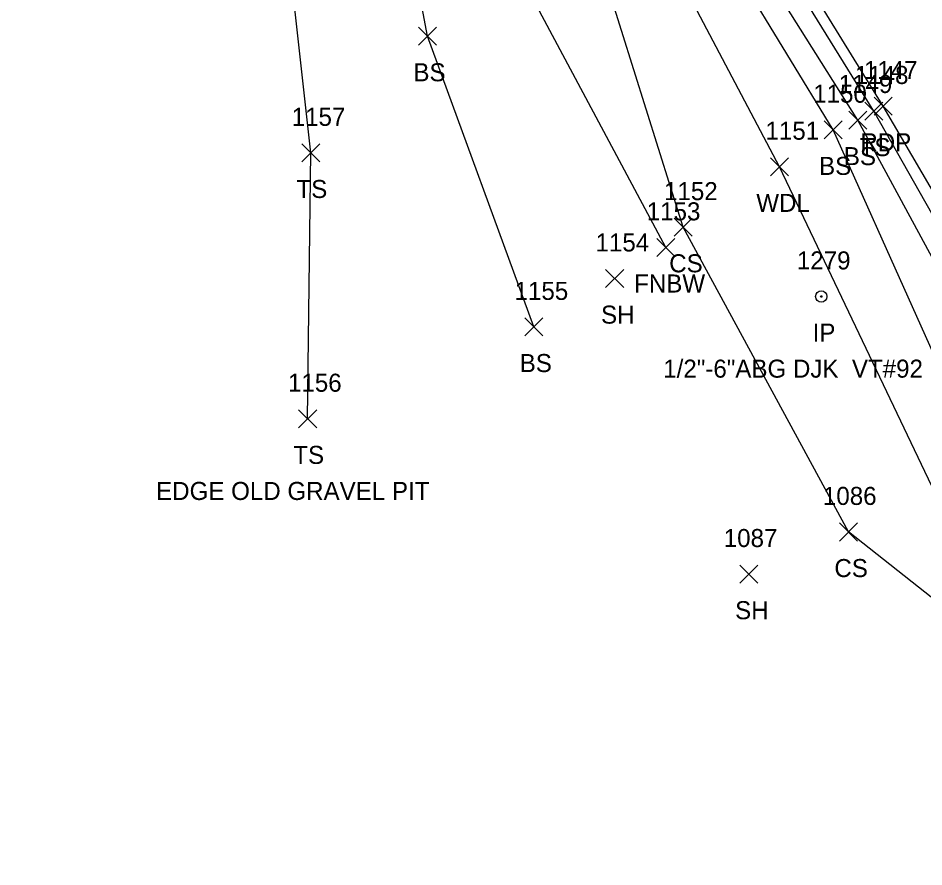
# Model space of a CAD drawing. Extents: x 1501299 to 1502485, y 381423 to 383765.
# Drawn here: x 1501751.5 to 1501851.9, y 382849.9 to 382944 of the extents above; entities that cross this region are included whole.
import ezdxf

# ---------------------------------------------------------------- set-up
doc = ezdxf.new("R2010")
doc.units = 0
for name, color, linetype in [('L_A', 7, 'Continuous'), ('L_C', 7, 'Continuous'), ('L_I', 7, 'Continuous'), ('L_TIC', 7, 'Continuous'), ('LAWA', 7, 'Continuous'), ('LELB', 7, 'Continuous'), ('LFNC', 7, 'Continuous'), ('M_A', 7, 'Continuous'), ('M_C', 7, 'Continuous'), ('M_I', 7, 'Continuous'), ('MPIR', 7, 'Continuous'), ('P_A', 7, 'Continuous'), ('P_I', 7, 'Continuous'), ('P_TIC', 7, 'Continuous'), ('PET', 7, 'Continuous')]:
    doc.layers.add(name, color=color, linetype=linetype)

msp = doc.modelspace()

# ---------------------------------------------------------------- linework, layer by layer
at = {"layer": 'L_TIC'}
for points in [[(1501795.88, 382941.03), (1501797.88, 382943.03)], [(1501797.88, 382941.03), (1501795.88, 382943.03)], [(1501845.4, 382932.73), (1501847.4, 382934.73)], [(1501847.4, 382932.73), (1501845.4, 382934.73)], [(1501843.62, 382931.73), (1501845.62, 382933.73)], [(1501845.62, 382931.73), (1501843.62, 382933.73)], [(1501840.87, 382930.65), (1501842.87, 382932.65)], [(1501842.87, 382930.65), (1501840.87, 382932.65)], [(1501782.94, 382928.09), (1501784.94, 382930.09)], [(1501784.94, 382928.09), (1501782.94, 382930.09)], [(1501834.93, 382926.55), (1501836.93, 382928.55)], [(1501836.93, 382926.55), (1501834.93, 382928.55)], [(1501824.25, 382919.85), (1501826.25, 382921.85)], [(1501826.25, 382919.85), (1501824.25, 382921.85)], [(1501822.33, 382917.61), (1501824.33, 382919.61)], [(1501824.33, 382917.61), (1501822.33, 382919.61)], [(1501816.64, 382914.16), (1501818.64, 382916.16)], [(1501818.64, 382914.16), (1501816.64, 382916.16)], [(1501807.67, 382908.79), (1501809.67, 382910.79)], [(1501809.67, 382908.79), (1501807.67, 382910.79)], [(1501782.59, 382898.61), (1501784.59, 382900.61)], [(1501784.59, 382898.61), (1501782.59, 382900.61)], [(1501842.57, 382886.06), (1501844.57, 382888.06)], [(1501844.57, 382886.06), (1501842.57, 382888.06)], [(1501831.51, 382881.39), (1501833.51, 382883.39)], [(1501833.51, 382881.39), (1501831.51, 382883.39)]]:
    msp.add_lwpolyline(points, dxfattribs=at)
at = {"layer": 'LAWA'}
msp.add_lwpolyline([(1501942.68, 382714.84), (1501935.18, 382744.72), (1501913.34, 382785.2), (1501893.39, 382826.43), (1501865.29, 382869.92), (1501854.75, 382888.13), (1501835.93, 382927.55), (1501822.23, 382953.47), (1501796.61, 382993.04), (1501779.61, 383024.31), (1501754.16, 383064.05), (1501733.53, 383095.14)], dxfattribs=at)
at = {"layer": 'LELB'}
for points in [[(1501947.07, 382716.2), (1501936.79, 382745.62), (1501921.74, 382787.5), (1501900.17, 382829.78), (1501877.02, 382875.8), (1501866.17, 382892.91), (1501844.62, 382932.73), (1501828.06, 382959.04), (1501805.27, 382995.6), (1501783.69, 383028.16), (1501760.13, 383067.52), (1501734.81, 383103.88), (1501716.07, 383128.73), (1501702.98, 383136.28), (1501694.19, 383132.72)], [(1501947.96, 382716.12), (1501940, 382745.7), (1501923.41, 382788.32), (1501902.81, 382830.43), (1501868.96, 382893.88), (1501846.4, 382933.73), (1501830.03, 382960.15), (1501806.63, 382996.69), (1501785.68, 383029.2), (1501761.09, 383068.04), (1501736.24, 383105.32), (1501718.86, 383131.58)], [(1501945.34, 382716.14), (1501936.67, 382745.19), (1501918.39, 382786.66), (1501897.88, 382827.99), (1501871.61, 382874.07), (1501860.42, 382890.26), (1501841.87, 382931.65), (1501826.47, 382956.95), (1501803.66, 382993.76), (1501782.06, 383026.73), (1501758.57, 383066.64), (1501733.62, 383102.86), (1501712.41, 383124.49), (1501694.92, 383122.17), (1501687.27, 383121.66)], [(1501783.59, 382899.61), (1501783.94, 382929.09), (1501780.21, 382962.68), (1501777.23, 382979.1), (1501762.26, 383002.32), (1501757.64, 383021.11), (1501754.69, 383033.79), (1501751.14, 383043.33), (1501742.41, 383064.13), (1501735.88, 383077.84), (1501726.8, 383086.93), (1501711.19, 383095.35), (1501693.41, 383100.22), (1501689.59, 383108.9)], [(1501865.29, 382869.92), (1501843.57, 382887.06), (1501825.25, 382920.85), (1501815.65, 382951.42), (1501792.13, 382984.56)], [(1501808.67, 382909.79), (1501796.88, 382942.03), (1501792.07, 382967.6), (1501777.23, 382979.1)]]:
    msp.add_lwpolyline(points, dxfattribs=at)
at = {"layer": 'LFNC'}
msp.add_lwpolyline([(1501823.33, 382918.61), (1501807, 382949.14), (1501792.13, 382984.56), (1501780.59, 382996.59)], dxfattribs=at)
at = {"layer": 'MPIR'}
for radius in [0.625, 0.0833]:
    msp.add_circle((1501840.55, 382913.17), radius, dxfattribs=at)
at = {"layer": 'P_TIC'}
for points in [[(1501846.41, 382933.27), (1501848.41, 382935.27)], [(1501848.41, 382933.27), (1501846.41, 382935.27)]]:
    msp.add_lwpolyline(points, dxfattribs=at)
at = {"layer": 'PET'}
msp.add_lwpolyline([(1501949.65, 382716.51), (1501941.04, 382745.98), (1501925.01, 382788.59), (1501904.25, 382831.62), (1501880.76, 382877.89), (1501870.56, 382894.72), (1501847.41, 382934.27), (1501830.94, 382961.01), (1501807.98, 382997.99), (1501787.08, 383029.95), (1501762.26, 383068.78), (1501737.38, 383106.29), (1501722.89, 383129.67), (1501696.7, 383166.34)], dxfattribs=at)

# ---------------------------------------------------------------- texts
at = {"layer": 'L_A'}
for s, p in [('BS', (1501795.32, 382937.03)), ('TS', (1501844.81, 382928.73)), ('BS', (1501843.06, 382927.73)), ('BS', (1501840.31, 382926.65)), ('TS', (1501782.35, 382924.09)), ('WDL', (1501833.35, 382922.55)), ('CS', (1501823.69, 382915.85)), ('FNBW', (1501819.8, 382913.61)), ('SH', (1501816.13, 382910.16)), ('BS', (1501807.11, 382904.79)), ('TS', (1501782, 382894.61)), ('CS', (1501842.01, 382882.06)), ('SH', (1501831, 382877.39))]:
    msp.add_text(s, height=2, dxfattribs=at).set_placement(p)
at = {"layer": 'L_C'}
msp.add_text('EDGE OLD GRAVEL PIT', height=2, dxfattribs=at).set_placement((1501766.78, 382890.61))
at = {"layer": 'L_I'}
for s, p in [('1148', (1501844.28, 382936.73)), ('1149', (1501842.49, 382935.73)), ('1150', (1501839.66, 382934.65)), ('1157', (1501781.82, 382932.09)), ('1151', (1501834.37, 382930.55)), ('1152', (1501823.12, 382923.85)), ('1153', (1501821.2, 382921.61)), ('1154', (1501815.52, 382918.16)), ('1155', (1501806.54, 382912.79)), ('1156', (1501781.41, 382902.61)), ('1086', (1501840.74, 382890.06)), ('1087', (1501829.74, 382885.39))]:
    msp.add_text(s, height=2, dxfattribs=at).set_placement(p)
at = {"layer": 'M_A'}
msp.add_text('IP', height=2, dxfattribs=at).set_placement((1501839.6, 382908.17))
at = {"layer": 'M_C'}
msp.add_text('1/2"-6"ABG DJK  VT#92', height=2, dxfattribs=at).set_placement((1501823.03, 382904.17))
at = {"layer": 'M_I'}
msp.add_text('1279', height=2, dxfattribs=at).set_placement((1501837.85, 382916.17))
at = {"layer": 'P_A'}
msp.add_text('RDP', height=2, dxfattribs=at).set_placement((1501844.89, 382929.27))
at = {"layer": 'P_I'}
msp.add_text('1147', height=2, dxfattribs=at).set_placement((1501845.28, 382937.27))

doc.saveas('drawing.dxf')
